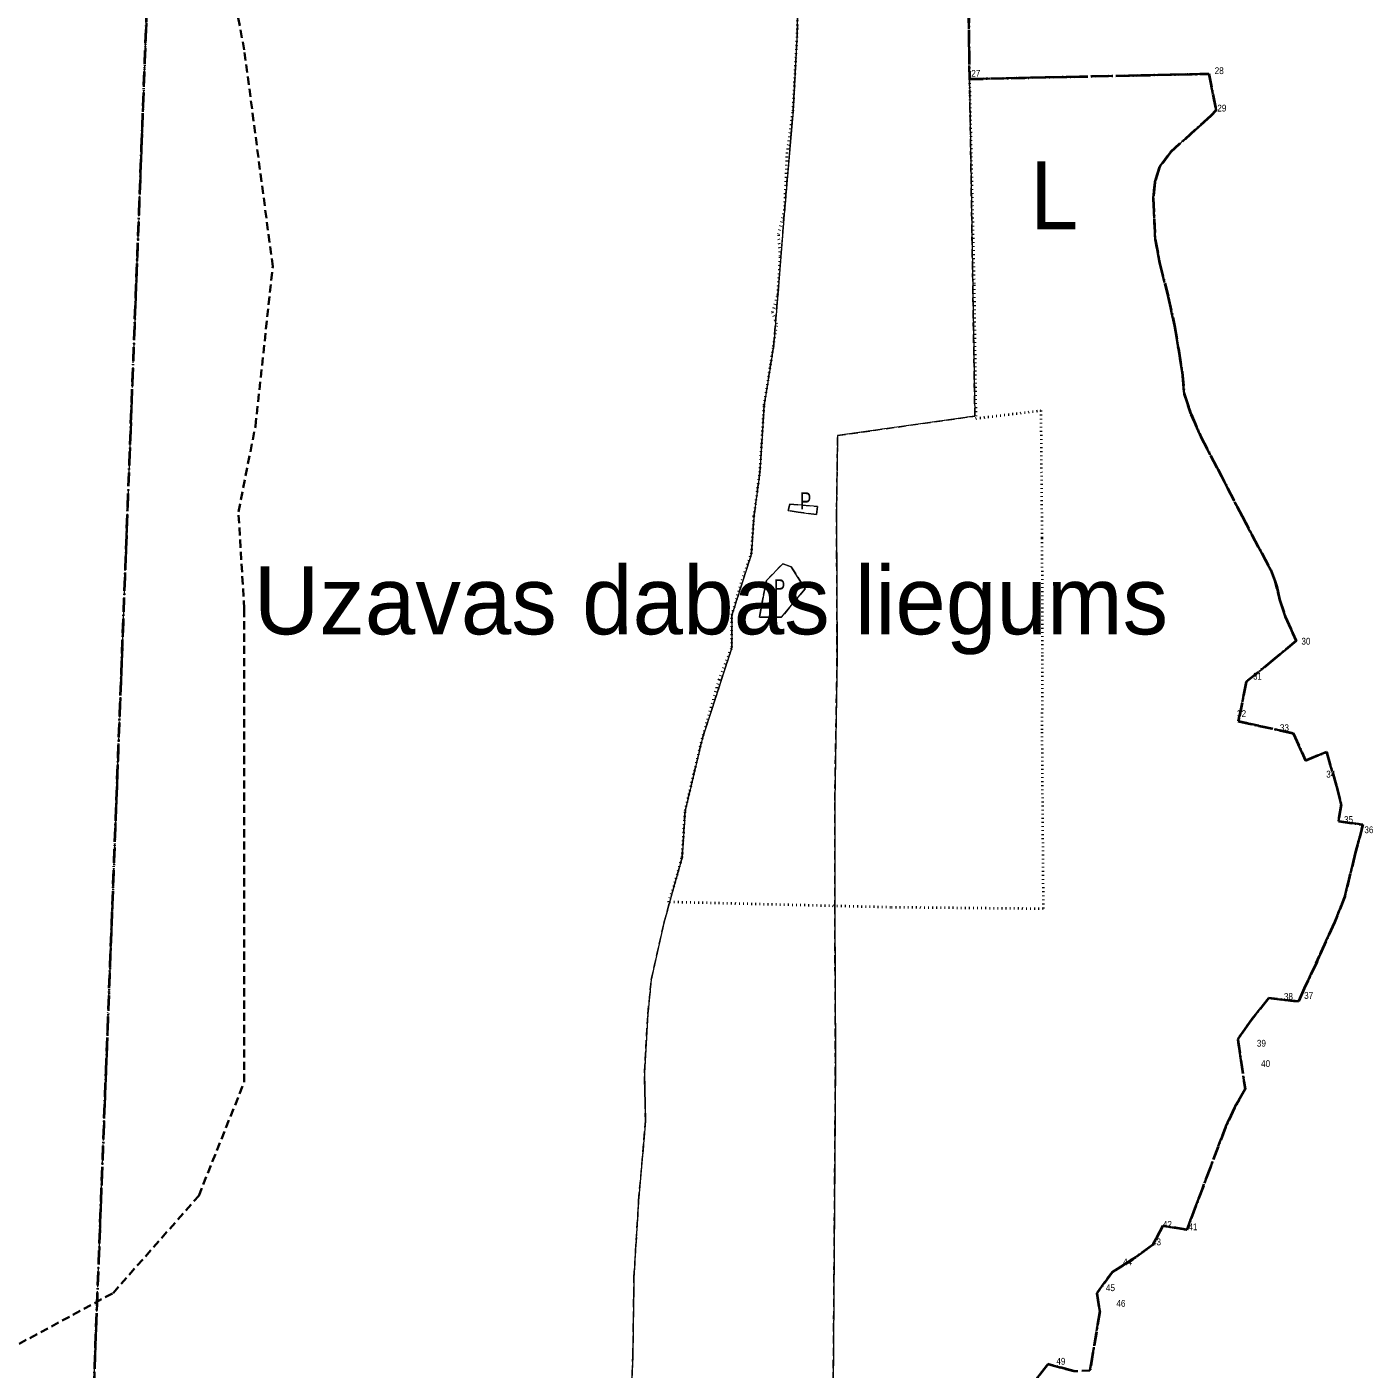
# Model space of a CAD drawing. Extents: x 338337 to 345629, y 338092 to 349945.
# Drawn here: x 341668 to 345629, y 341315 to 345265 of the extents above; entities that cross this region are included whole.
import ezdxf

# ---------------------------------------------------------------- set-up
doc = ezdxf.new("R2010")
doc.units = 0
doc.header["$LTSCALE"] = 8
for name, pattern in [('DASH_DOUBLE_DOT', [9.2, 5, -1.2, 0.3, -1.2, 0.3, -1.2]), ('DOT_DASHED', [7.7, 5, -1.2, 0.3, -1.2]), ('DOTTED', [1.5, 0.3, -1.2]), ('MEDIUM_DASHED', [4.5, 3, -1.5])]:
    doc.linetypes.add(name, pattern=pattern)
for name, color, linetype, lineweight in [('26', 7, 'DASH_DOUBLE_DOT', 35), ('28', 7, 'Continuous', 13), ('30', 7, 'DOT_DASHED', 40), ('31', 7, 'MEDIUM_DASHED', 13), ('32', 7, 'MEDIUM_DASHED', 13), ('33', 7, 'MEDIUM_DASHED', 13), ('34', 7, 'DOTTED', 40), ('35', 7, 'MEDIUM_DASHED', 35)]:
    doc.layers.add(name, color=color, linetype=linetype, lineweight=lineweight)
for name, color, linetype in [('27', 7, 'Continuous'), ('29', 7, 'Continuous'), ('36', 7, 'Continuous')]:
    doc.layers.add(name, color=color, linetype=linetype)

msp = doc.modelspace()

# ---------------------------------------------------------------- linework, layer by layer
at = {"layer": '26'}
for points in [[(343976.39, 349474.549), (342197.475, 349919.528), (342109.457, 347629.74), (342004.932, 344909.777), (341900.436, 342189.822), (341795.969, 339469.876), (341744.602, 338132.109), (343155.288, 338130.097)], [(344441.327, 345112.197), (344426.979, 346118.809)], [(344795.984, 341310.949), (344824.663, 341485.966), (344815.897, 341538.611), (344861.447, 341600.723), (344921.558, 341638.326), (344981.036, 341681.095), (345010.736, 341736.76), (345080.87, 341725.076), (345194.74, 342027.6), (345221.164, 342084.434), (345252.89, 342138.859), (345230.816, 342285.545), (345266.204, 342337.667), (345321.414, 342406.906), (345409.445, 342396.833), (345426.48, 342435.872), (345463.121, 342513.137), (345515.398, 342629.598), (345545.627, 342706.589), (345576.871, 342833.601), (345598.769, 342917.82), (345527.088, 342927.744), (345534.78, 342977.067), (345521.63, 343030.761), (345491.721, 343131.465), (345430.342, 343106.845), (345394.237, 343186.766), (345232.547, 343221.723), (345256.035, 343337.518), (345339.312, 343405.77), (345403.231, 343458.157), (345392.052, 343482.251), (345370.787, 343530.454), (345353.502, 343580.523), (345350.092, 343598.893), (345345.741, 343617.689), (345340.337, 343635.535), (345327.827, 343666.988), (345301.403, 343716.537), (345243.416, 343825.268), (345172.731, 343962.783), (345122.358, 344058.581), (345093.448, 344125.343), (345073.306, 344185.097), (345067.184, 344249.698), (345057.269, 344311.794), (345044.574, 344385.804), (345026.399, 344469.987), (345000.99, 344571.059), (344987.623, 344639.609), (344982.045, 344761.603), (344986.553, 344808.406), (345000.787, 344853.416), (345032.953, 344896.897), (345151.47, 345003.301), (345167.192, 345020.612), (345145.578, 345127.42), (344441.327, 345112.197)], [(344585.47, 341216.478), (344672.004, 341329.751), (344748.271, 341309.232)]]:
    msp.add_lwpolyline(points, dxfattribs=at)
at = {"layer": '28'}
for points in [[(343939.615, 345740.597), (343934.614, 345245.261), (343922.113, 345017.607), (343897.11, 344724.909), (343877.107, 344477.241), (343864.605, 344324.637), (343837.101, 344152.021), (343824.6, 343954.387), (343807.098, 343824.299), (343799.597, 343714.223), (343742.089, 343534.101), (343742.089, 343439.037), (343654.578, 343168.855), (343604.571, 342958.711), (343595.508, 342820.493), (343571.13, 342734.811), (343542.201, 342628.083), (343504.888, 342461.939), (343494.712, 342360.217), (343484.536, 342187.289), (343487.928, 342044.879), (343467.575, 341810.921), (343454.007, 341587.133), (343450.615, 341353.173), (343443.831, 341193.811)], [(344441.327, 345112.197), (344457.063, 344119.784), (344053.154, 344062.574), (344050.305, 343853.171), (344049.994, 343822.032), (344051.541, 343412.126), (344044.847, 342988.406), (344044.846, 342671.198), (344046.608, 342221.819), (344044.846, 341927.52), (344034.278, 340454.262), (344032.516, 339737.018), (343775.322, 339742.305), (343777.084, 338942.234), (343777.034, 338119.48)]]:
    msp.add_lwpolyline(points, dxfattribs=at)
for points in [[(343912.711, 343860.569), (343908.21, 343841.995), (343937.467, 343836.929), (343990.917, 343830.738), (343994.293, 343853.815)], [(343835.108, 343593.31), (343823.18, 343528.455), (343888.017, 343527.971), (343958.161, 343611.905), (343917.022, 343676.147), (343891.742, 343685.386), (343843.557, 343636.288)]]:
    msp.add_lwpolyline(points, close=True, dxfattribs=at)
at = {"layer": '30'}
for points in [[(343155.288, 338130.097), (341744.602, 338132.109), (341795.969, 339469.876), (341900.436, 342189.822), (342004.932, 344909.777), (342109.457, 347629.74)], [(344426.979, 346118.809), (344441.327, 345112.197), (345145.578, 345127.42), (345167.192, 345020.612), (345151.47, 345003.301), (345032.953, 344896.897), (345000.787, 344853.416), (344986.553, 344808.406), (344982.045, 344761.603), (344987.623, 344639.609), (345000.99, 344571.059), (345026.399, 344469.987), (345044.574, 344385.804), (345057.269, 344311.794), (345067.184, 344249.698), (345073.306, 344185.097), (345093.448, 344125.343), (345122.358, 344058.581), (345172.731, 343962.783), (345243.416, 343825.268), (345301.403, 343716.537), (345327.827, 343666.988), (345340.337, 343635.535), (345345.741, 343617.689), (345350.092, 343598.893), (345353.502, 343580.523), (345370.787, 343530.454), (345392.052, 343482.251), (345403.231, 343458.157), (345339.312, 343405.77), (345256.035, 343337.518), (345232.547, 343221.723), (345394.237, 343186.766), (345430.342, 343106.845), (345491.721, 343131.465), (345521.63, 343030.761), (345534.78, 342977.067), (345527.088, 342927.744), (345598.769, 342917.82), (345576.871, 342833.601), (345545.627, 342706.589), (345515.398, 342629.598), (345463.121, 342513.137), (345426.48, 342435.872), (345409.445, 342396.833), (345321.414, 342406.906), (345266.204, 342337.667), (345230.816, 342285.545), (345252.89, 342138.859)], [(345252.89, 342138.859), (345221.164, 342084.434), (345194.74, 342027.6), (345080.87, 341725.076), (345010.736, 341736.76), (344981.036, 341681.095), (344921.558, 341638.326), (344861.447, 341600.723), (344815.897, 341538.611), (344824.663, 341485.966), (344795.984, 341310.949)], [(344748.271, 341309.232), (344672.004, 341329.751), (344585.47, 341216.478)]]:
    msp.add_lwpolyline(points, dxfattribs=at)
at = {"layer": '31'}
for points in [[(344426.979, 346118.809), (344441.327, 345112.197), (344457.063, 344119.784), (344053.154, 344062.574), (344050.305, 343853.171), (344049.994, 343822.032), (344051.541, 343412.126), (344044.847, 342988.406), (344044.846, 342671.198), (344046.608, 342221.819), (344044.846, 341927.52), (344034.278, 340454.262)], [(343443.831, 341193.811), (343450.615, 341353.173), (343454.007, 341587.133), (343467.575, 341810.921), (343487.928, 342044.879), (343484.536, 342187.289), (343494.712, 342360.217), (343504.888, 342461.939), (343542.201, 342628.083), (343571.13, 342734.811), (343595.508, 342820.493), (343604.571, 342958.711), (343654.578, 343168.855), (343742.089, 343439.037), (343742.089, 343534.101), (343799.597, 343714.223), (343807.098, 343824.299), (343824.6, 343954.387), (343837.101, 344152.021), (343864.605, 344324.637), (343877.107, 344477.241), (343897.11, 344724.909), (343922.113, 345017.607), (343934.614, 345245.261), (343939.615, 345740.597)]]:
    msp.add_lwpolyline(points, dxfattribs=at)
for points in [[(343912.711, 343860.569), (343994.293, 343853.815), (343990.917, 343830.738), (343937.467, 343836.929), (343908.21, 343841.995)], [(343835.108, 343593.31), (343843.557, 343636.288), (343891.742, 343685.386), (343917.022, 343676.147), (343958.161, 343611.905), (343888.017, 343527.971), (343823.18, 343528.455)]]:
    msp.add_lwpolyline(points, close=True, dxfattribs=at)
at = {"layer": '32'}
for points in [[(341795.969, 339469.876), (341900.436, 342189.822), (342004.932, 344909.777), (342109.457, 347629.74)], [(343939.615, 345740.597), (343934.614, 345245.261), (343922.113, 345017.607), (343897.11, 344724.909), (343877.107, 344477.241), (343864.605, 344324.637), (343837.101, 344152.021), (343824.6, 343954.387), (343807.098, 343824.299), (343799.597, 343714.223), (343742.089, 343534.101), (343742.089, 343439.037), (343654.578, 343168.855), (343604.571, 342958.711), (343595.508, 342820.493), (343571.13, 342734.811), (343542.201, 342628.083), (343504.888, 342461.939), (343494.712, 342360.217), (343484.536, 342187.289), (343487.928, 342044.879), (343467.575, 341810.921), (343454.007, 341587.133), (343450.615, 341353.173), (343443.831, 341193.811)], [(344034.278, 340454.262), (344044.846, 341927.52), (344046.608, 342221.819), (344044.846, 342671.198), (344044.847, 342988.406), (344051.541, 343412.126), (344049.994, 343822.032), (344050.305, 343853.171), (344053.154, 344062.574), (344457.063, 344119.784), (344441.327, 345112.197), (345145.578, 345127.42), (345167.192, 345020.612), (345151.47, 345003.301), (345032.953, 344896.897), (345000.787, 344853.416), (344986.553, 344808.406), (344982.045, 344761.603), (344987.623, 344639.609), (345000.99, 344571.059), (345026.399, 344469.987), (345044.574, 344385.804), (345057.269, 344311.794), (345067.184, 344249.698), (345073.306, 344185.097), (345093.448, 344125.343), (345122.358, 344058.581), (345172.731, 343962.783), (345243.416, 343825.268), (345301.403, 343716.537), (345327.827, 343666.988), (345340.337, 343635.535), (345345.741, 343617.689), (345350.092, 343598.893), (345353.502, 343580.523), (345370.787, 343530.454), (345392.052, 343482.251), (345403.231, 343458.157), (345339.312, 343405.77), (345256.035, 343337.518), (345232.547, 343221.723), (345394.237, 343186.766), (345430.342, 343106.845), (345491.721, 343131.465), (345521.63, 343030.761), (345534.78, 342977.067), (345527.088, 342927.744), (345598.769, 342917.82)], [(345598.769, 342917.82), (345576.871, 342833.601), (345545.627, 342706.589), (345515.398, 342629.598), (345463.121, 342513.137), (345426.48, 342435.872), (345409.445, 342396.833), (345321.414, 342406.906), (345266.204, 342337.667), (345230.816, 342285.545), (345252.89, 342138.859), (345221.164, 342084.434), (345194.74, 342027.6), (345080.87, 341725.076), (345010.736, 341736.76), (344981.036, 341681.095), (344921.558, 341638.326), (344861.447, 341600.723), (344815.897, 341538.611), (344824.663, 341485.966), (344795.984, 341310.949)], [(344748.271, 341309.232), (344672.004, 341329.751), (344585.47, 341216.478)]]:
    msp.add_lwpolyline(points, dxfattribs=at)
at = {"layer": '33'}
for points in [[(343912.711, 343860.569), (343994.293, 343853.815), (343990.917, 343830.738), (343937.467, 343836.929), (343908.21, 343841.995)], [(343835.108, 343593.31), (343843.557, 343636.288), (343891.742, 343685.386), (343917.022, 343676.147), (343958.161, 343611.905), (343888.017, 343527.971), (343823.18, 343528.455)]]:
    msp.add_lwpolyline(points, close=True, dxfattribs=at)
at = {"layer": '34'}
msp.add_lwpolyline([(344426.979, 346118.809), (344441.327, 345112.197), (344455.031, 344506), (344460.031, 344113.234), (344651.306, 344136.375), (344654.431, 343760.495), (344655.681, 343415.261), (344654.431, 343189.483), (344658.182, 342669.756), (344209.373, 342674.134), (343556.162, 342689.77), (343571.164, 342735.426), (343595.542, 342821.109), (343604.605, 342959.327), (343654.612, 343169.47), (343704.618, 343344.588), (343742.123, 343439.653), (343742.123, 343534.717), (343772.127, 343637.287), (343799.631, 343714.839), (343807.132, 343824.914), (343824.634, 343955.002), (343837.135, 344152.636), (343864.639, 344325.253), (343874.641, 344390.297), (343862.139, 344425.32), (343877.141, 344477.856), (343884.642, 344590.432), (343879.641, 344655.476), (343897.144, 344725.524), (343904.645, 344893.137), (343922.147, 345018.222), (343934.648, 345245.876), (343939.649, 345741.212)], dxfattribs=at)
at = {"layer": '35'}
for points in [[(344422.342, 346886.381), (344426.979, 346118.809), (344441.327, 345112.197), (345145.578, 345127.42), (345167.192, 345020.612)], [(341518, 341321), (341921, 341539), (342173, 341825), (342307, 342160), (342307, 342664), (342307, 343553), (342290, 343838), (342340, 344090), (342391, 344560), (342307, 345198), (342206, 345734)], [(345167.192, 345020.612), (345151.47, 345003.301), (345115, 344970), (345046, 344909)], [(345046, 344909), (345032.953, 344896.897), (345000.787, 344853.416), (344994, 344832), (344986.553, 344808.406)], [(344986.553, 344808.406), (344982.045, 344761.603), (344987.623, 344639.609)], [(344987.623, 344639.609), (345000.99, 344571.059), (345026.399, 344469.987), (345044.574, 344385.804), (345067, 344250), (345073, 344185), (345093, 344125), (345122, 344059), (345250, 343813), (345328, 343667)], [(345328, 343667), (345340.337, 343635.535), (345354, 343581)], [(345354, 343581), (345370.787, 343530.454), (345380, 343510), (345403.231, 343458.157), (345256, 343338), (345233, 343222), (345394.237, 343186.766), (345430.342, 343106.845), (345491.721, 343131.465)], [(345491.721, 343131.465), (345521.63, 343030.761), (345535, 342977), (345527, 342928), (345599, 342918)], [(345599, 342918), (345576.871, 342833.601), (345546, 342707)], [(345546, 342707), (345515.398, 342629.598), (345449, 342484)], [(345449, 342484), (345426.48, 342435.872), (345409.445, 342396.833), (345321.414, 342406.906)], [(345321.414, 342406.906), (345266.204, 342337.667), (345230.816, 342285.545), (345252.89, 342138.859)], [(345252.89, 342138.859), (345221.164, 342084.434), (345194.74, 342027.6), (345125, 341842), (345080.87, 341725.076), (345010.736, 341736.76)], [(345010.736, 341736.76), (344981.036, 341681.095), (344922, 341638), (344861, 341601), (344816, 341539), (344825, 341486), (344796, 341311), (344748, 341309), (344672, 341330), (344585, 341216), (344585, 341170), (344584, 341151), (344605, 341099), (344600, 341083), (344575, 340993), (344560, 340946), (344627, 340866), (344653, 340863), (344751, 340854)]]:
    msp.add_lwpolyline(points, dxfattribs=at)

# ---------------------------------------------------------------- texts
at = {"layer": '27'}
msp.add_text('Uzavas dabas liegums', height=200, dxfattribs=at).set_placement((342335.151, 343477.809))
at = {"layer": '29'}
for s, height, width, p in [('L', 200, 0.95, (344620.105, 344669.415)), ('P', 50, 0.75, (343942.44, 343845.784)), ('P', 50, 0.75, (343865.8, 343589.703))]:
    msp.add_text(s, height=height, dxfattribs=dict(at, width=width)).set_placement(p)
at = {"layer": '36'}
for s, width, p in [('27', 0.9, (344446.582, 345118.799)), ('28', 0.9, (345162.876, 345126.546)), ('29', 0.9, (345170.567, 345016.401)), ('30', 0.9, (345418.127, 343447.44)), ('31', 0.85, (345276.32, 343344.51)), ('32', 0.9, (345228.694, 343234.476)), ('33', 0.9, (345354.799, 343192.96)), ('34', 0.9, (345491.187, 343056.077)), ('35', 0.9, (345543.405, 342922.769)), ('36', 0.9, (345603.378, 342892.52)), ('38', 0.9, (345366.57, 342402.131)), ('37', 0.9, (345426.173, 342404.921)), ('39', 0.9, (345287.072, 342264.224)), ('40', 0.9, (345299.422, 342204.217)), ('42', 0.9, (345010.234, 341731.11)), ('41', 0.85, (345086.531, 341724.005)), ('43', 0.9, (344978.239, 341679.678)), ('44', 0.9, (344893.328, 341620.575)), ('45', 0.9, (344842.785, 341544.767)), ('46', 0.9, (344873.638, 341498.675)), ('49', 0.9, (344696.922, 341328.308))]:
    msp.add_text(s, height=20, dxfattribs=dict(at, width=width)).set_placement(p)

doc.saveas('drawing.dxf')
